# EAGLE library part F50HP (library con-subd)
SUB-D
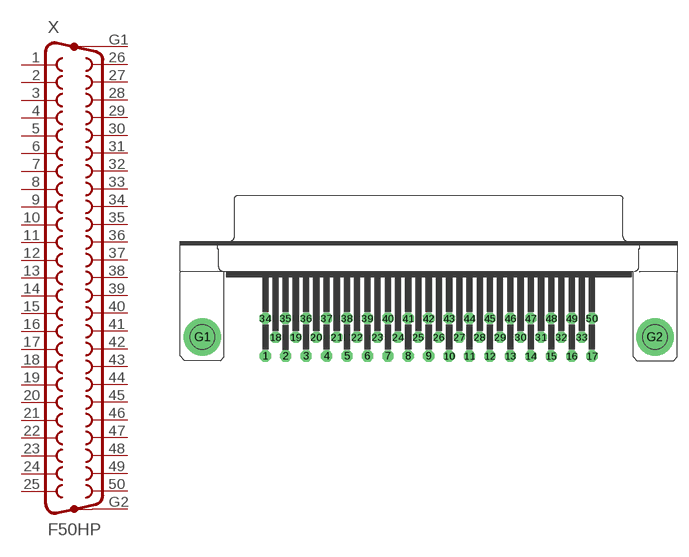
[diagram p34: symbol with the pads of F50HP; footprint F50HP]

Designator prefix X

## F50HP (OC_FARNELL: unknown; OC_NEWARK: unknown)  [F50HP]
1  1  pas
2  2  pas
3  3  pas
4  4  pas
5  5  pas
6  6  pas
7  7  pas
8  8  pas
9  9  pas
10  10  pas
11  11  pas
12  12  pas
13  13  pas
14  14  pas
15  15  pas
16  16  pas
17  17  pas
18  18  pas
19  19  pas
20  20  pas
21  21  pas
22  22  pas
23  23  pas
24  24  pas
25  25  pas
26  26  pas
27  27  pas
28  28  pas
29  29  pas
30  30  pas
31  31  pas
32  32  pas
33  33  pas
34  34  pas
35  35  pas
36  36  pas
37  37  pas
38  38  pas
39  39  pas
40  40  pas
41  41  pas
42  42  pas
43  43  pas
44  44  pas
45  45  pas
46  46  pas
47  47  pas
48  48  pas
49  49  pas
50  50  pas
G1  G1  pas
G2  G2  pas

## Footprint F50HP (pad centres in mm)
SUB-D
drill 1.016 octagon: 1 -22.073,-2.54; 2 -19.329,-2.54; 3 -16.561,-2.54; 4 -13.792,-2.54; 5 -11.049,-2.54; 6 -8.28,-2.54; 7 -5.512,-2.54; 8 -2.769,-2.54; 9 0,-2.54; 10 2.769,-2.54; 11 5.512,-2.54; 12 8.28,-2.54; 13 11.049,-2.54; 14 13.792,-2.54; 15 16.561,-2.54; 16 19.329,-2.54; 17 22.073,-2.54; 18 -20.701,0; 19 -17.958,0; 20 -15.189,0; 21 -12.421,0; 22 -9.677,0; 23 -6.909,0; 24 -4.14,0; 25 -1.397,0; 26 1.372,0; 27 4.14,0; 28 6.883,0; 29 9.652,0; 30 12.421,0; 31 15.189,0; 32 17.932,0; 33 20.701,0; 34 -22.073,2.54; 35 -19.329,2.54; 36 -16.561,2.54; 37 -13.792,2.54; 38 -11.049,2.54; 39 -8.28,2.54; 40 -5.512,2.54; 41 -2.769,2.54; 42 0,2.54; 43 2.769,2.54; 44 5.512,2.54; 45 8.28,2.54; 46 11.049,2.54; 47 13.792,2.54; 48 16.561,2.54; 49 19.329,2.54; 50 22.073,2.54
drill 3.302 pad 5.08 round: G1 -30.556,0; G2 30.556,0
